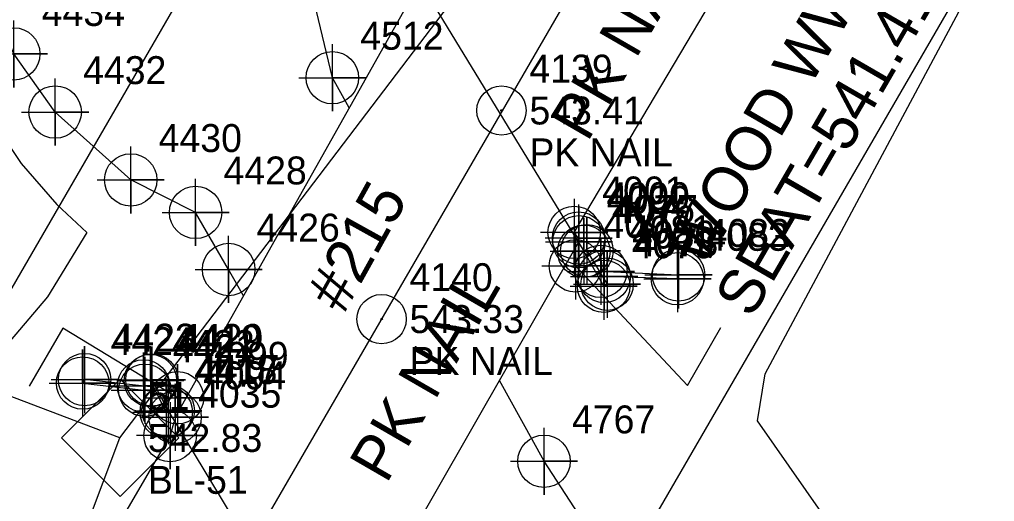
# Model space of a CAD drawing. Extents: x 1653123 to 1656194, y 596584 to 600233.
# Drawn here: x 1653723.1 to 1653810.3, y 598013.1 to 598056.2 of the extents above; entities that cross this region are included whole.
import ezdxf

# ---------------------------------------------------------------- set-up
doc = ezdxf.new("R2010")
doc.units = 0
for name, color, linetype in [('CTL Supplemental Horizontal and Vertical CELL', 7, 'Continuous'), ('CTL Supplemental Horizontal and Vertical Cogo Comment', 7, 'Continuous'), ('CTL Supplemental Horizontal and Vertical Cogo Elevation', 7, 'Continuous'), ('CTL Supplemental Horizontal and Vertical Cogo Number', 7, 'Continuous'), ('Exist Horizontal Alignment', 7, 'Continuous'), ('Exist Horizontal Baseline Alignment', 7, 'Continuous'), ('Exist Horizontal Baseline Alignment Station Label', 7, 'Continuous'), ('Exist Hydro Jurisdictional Stream or Body of Water', 7, 'Continuous'), ('Exist Hydro Stream or Body of Water Cogo Number', 7, 'Continuous'), ('Exist Property Iron Pin CELL', 7, 'Continuous'), ('Exist Property Iron Pin Cogo Comment', 7, 'Continuous'), ('Exist Property Iron Pin Cogo Elevation', 7, 'Continuous'), ('Exist Property Iron Pin Cogo Number', 7, 'Continuous'), ('Exist Property Iron Pin Text', 7, 'Continuous'), ('Exist Right of Way Line', 7, 'Continuous'), ('Exist Roads EOP Cogo Point CELL', 7, 'Continuous'), ('Exist Structure Major Bridge Seat Top Elevation', 7, 'Continuous'), ('Exist Structure Major Bridge WW Text', 7, 'Continuous'), ('Exist Structure Major Deck Tunnel Box Culvert', 7, 'Continuous'), ('Exist Structure Major Deck Tunnel Box Culvert Text', 7, 'Continuous'), ('Exist Vegetation Woods Line', 7, 'Continuous'), ('Prop Approach Slab Hatching', 7, 'Continuous'), ('Prop Conc Shoulder Berm Gutter', 7, 'Continuous'), ('Prop Guardrail Anchor Unit CELL', 7, 'Continuous'), ('Prop Horizontal Alignment', 7, 'Continuous'), ('Prop Horizontal Alignment Station Label', 7, 'Continuous'), ('Prop Horizontal Alignment Tick Label', 7, 'Continuous'), ('Prop Horizontal Alignment Tick Large', 7, 'Continuous'), ('Prop Horizontal Alignment Tick Small', 7, 'Continuous'), ('Prop Roadway Bridge', 7, 'Continuous'), ('Prop Superelevation  Arrow CELL', 7, 'Continuous')]:
    doc.layers.add(name, color=color, linetype=linetype)

msp = doc.modelspace()

# ---------------------------------------------------------------- linework, layer by layer
at = {"layer": 'CTL Supplemental Horizontal and Vertical CELL'}
msp.add_line((1653732.119, 598018.788), (1653732.119, 598018.788), dxfattribs=at)
msp.add_line((1653732.119, 598018.788), (1653732.119, 598018.788), dxfattribs=at)
msp.add_lwpolyline([(1653726.904, 598018.806), (1653732.146, 598024.047), (1653737.396, 598018.797), (1653732.155, 598013.556)], close=True, dxfattribs=at)
msp.add_lwpolyline([(1653726.904, 598018.806), (1653732.146, 598024.047), (1653737.396, 598018.797), (1653732.155, 598013.556)], close=True, dxfattribs=at)
at = {"layer": 'Exist Horizontal Alignment'}
msp.add_line((1653731.562, 597988.043), (1653850.42, 598193.455), dxfattribs=at)
at = {"layer": 'Exist Horizontal Baseline Alignment'}
for p, q in [((1653732.119, 598018.788), (1653909.758, 598252.908)), ((1653570.02, 597590.969), (1653732.119, 598018.788))]:
    msp.add_line(p, q, dxfattribs=at)
at = {"layer": 'Exist Horizontal Baseline Alignment Station Label'}
msp.add_line((1653732.119, 598018.788), (1653694.859, 598032.906), dxfattribs=at)
at = {"layer": 'Exist Hydro Jurisdictional Stream or Body of Water'}
for points in [[(1653752.596, 598048.33), (1653751.106, 598051.034), (1653748.622, 598061.502), (1653747.508, 598068.196), (1653746.66, 598076.934), (1653747.243, 598081.733), (1653747.986, 598099.401), (1653743.287, 598114.123), (1653741.057, 598120.621)], [(1653743.157, 598031.517), (1653741.838, 598033.867), (1653738.884, 598038.977), (1653733.087, 598041.881), (1653726.332, 598047.958), (1653722.632, 598053.165), (1653719.921, 598059.44), (1653713.165, 598067.917), (1653711.556, 598075.693), (1653711.811, 598079.729), (1653711.131, 598085.335)], [(1653740.514, 597810.783), (1653744.472, 597825.192), (1653752.654, 597842.937), (1653766.87, 597862.079), (1653774.242, 597884.581), (1653779.209, 597901.216), (1653784.802, 597926.151), (1653788.222, 597952.968), (1653784.153, 597976.205), (1653781.486, 597999.079), (1653770.026, 598016.697), (1653766.044, 598023.924)]]:
    msp.add_lwpolyline(points, dxfattribs=at)
at = {"layer": 'Exist Property Iron Pin CELL'}
for centre, radius in [((1653766.224, 598048.096), 2.203), ((1653766.224, 598048.096), 2.203), ((1653766.224, 598048.096), 0.0707), ((1653766.224, 598048.096), 0.0707), ((1653755.508, 598029.427), 2.203), ((1653755.508, 598029.427), 2.203), ((1653755.508, 598029.427), 0.0707), ((1653755.508, 598029.427), 0.0707)]:
    msp.add_circle(centre, radius, dxfattribs=at)
at = {"layer": 'Exist Right of Way Line'}
for p, q in [((1653705.596, 598003.068), (1653824.453, 598208.48)), ((1653757.529, 597973.018), (1653876.386, 598178.43))]:
    msp.add_line(p, q, dxfattribs=at)
at = {"layer": 'Exist Roads EOP Cogo Point CELL'}
for points in [[(1653772.726, 598040.188), (1653772.726, 598034.188), (1653772.726, 598037.188), (1653775.726, 598037.188), (1653769.726, 598037.188)], [(1653773.119, 598039.676), (1653773.119, 598033.676), (1653773.119, 598036.676), (1653776.119, 598036.676), (1653770.119, 598036.676)], [(1653736.607, 598022), (1653736.607, 598016), (1653736.607, 598019), (1653739.607, 598019), (1653733.607, 598019)]]:
    msp.add_lwpolyline(points, dxfattribs=at)
for centre in [(1653772.726, 598037.188), (1653773.119, 598036.676), (1653736.607, 598019)]:
    msp.add_circle(centre, 2.344, dxfattribs=at)
at = {"layer": 'Exist Structure Major Bridge Seat Top Elevation'}
for points in [[(1653772.836, 598034.184), (1653782.838, 598023.471), (1653785.845, 598028.663)], [(1653737.263, 598022.388), (1653727.026, 598028.604), (1653724.02, 598023.412)]]:
    msp.add_lwpolyline(points, dxfattribs=at)
at = {"layer": 'Exist Structure Major Deck Tunnel Box Culvert'}
for points in [[(1653758.793, 598059.369), (1653737.049, 598020.636)], [(1653750.814, 597997.291), (1653773.15, 598036.35)]]:
    msp.add_lwpolyline(points, dxfattribs=at)
at = {"layer": 'Exist Vegetation Woods Line'}
for points in [[(1653772.69, 597855.659), (1653780.909, 597872.984), (1653787.83, 597901.293), (1653791.961, 597923.72), (1653796.55, 597945.524), (1653799.728, 597979.56), (1653801.787, 597996.223), (1653796.294, 598010.028), (1653789.109, 598020.31), (1653789.788, 598024.526), (1653810.305, 598062.923), (1653854.435, 598139.764), (1653881.65, 598185.926), (1653890.132, 598190.266), (1653890.781, 598172.436), (1653888.254, 598125.228), (1653881.516, 598039.211), (1653880.393, 597979.917), (1653882.927, 597907.141), (1653887.551, 597812.438), (1653892.774, 597769.351), (1653892.797, 597738.525)], [(1653717.78, 598061.155), (1653719.712, 598048.676), (1653723.279, 598043.338), (1653726.476, 598039.693), (1653729.156, 598037.169), (1653725.66, 598031.427), (1653686.391, 597985.111), (1653672.043, 597936.27), (1653661.326, 597915.511)]]:
    msp.add_lwpolyline(points, dxfattribs=at)
at = {"layer": 'Prop Approach Slab Hatching'}
for points in [[(1653769.836, 598034.184), (1653775.836, 598034.184), (1653772.836, 598034.184), (1653772.836, 598037.184), (1653772.836, 598031.184)], [(1653734.263, 598022.388), (1653740.263, 598022.388), (1653737.263, 598022.388), (1653737.263, 598025.388), (1653737.263, 598019.388)]]:
    msp.add_lwpolyline(points, dxfattribs=at)
for centre in [(1653772.836, 598034.184), (1653737.263, 598022.388)]:
    msp.add_circle(centre, 2.344, dxfattribs=at)
at = {"layer": 'Prop Conc Shoulder Berm Gutter'}
for points in [[(1653773.15, 598036.35), (1653773.119, 598036.676), (1653772.726, 598037.188), (1653794.44, 598073.843), (1653816.897, 598112.323), (1653839.541, 598150.793), (1653856.887, 598180.317), (1653871.823, 598206.021), (1653894.448, 598243.912), (1653917.39, 598282.615), (1653941.959, 598322.784), (1653953.154, 598342.488), (1653957.769, 598344.372), (1653957.983, 598346.456), (1653959.261, 598348.625), (1653971.076, 598367.128), (1653990.971, 598397.837)], [(1653736.935, 598020.212), (1653736.607, 598019), (1653719.197, 597989.182), (1653700.606, 597956.072), (1653684.638, 597926.74), (1653670.295, 597899.629), (1653655.341, 597870.975), (1653640.409, 597841.446), (1653625.564, 597809.568), (1653616.437, 597790.926), (1653615.549, 597790.139), (1653613.35, 597786.395), (1653606.899, 597772.908), (1653600.392, 597757.831), (1653598.645, 597751.546), (1653587.792, 597725.217), (1653577.727, 597701.576), (1653574.752, 597692.208), (1653558.963, 597651.013), (1653542.076, 597605.708)]]:
    msp.add_lwpolyline(points, dxfattribs=at)
at = {"layer": 'Prop Guardrail Anchor Unit CELL'}
for points in [[(1653719.632, 598053.165), (1653725.632, 598053.165), (1653722.632, 598053.165), (1653722.632, 598050.165), (1653722.632, 598056.165)], [(1653748.106, 598051.034), (1653754.106, 598051.034), (1653751.106, 598051.034), (1653751.106, 598048.034), (1653751.106, 598054.034)], [(1653723.332, 598047.958), (1653729.332, 598047.958), (1653726.332, 598047.958), (1653726.332, 598044.958), (1653726.332, 598050.958)], [(1653730.087, 598041.881), (1653736.087, 598041.881), (1653733.087, 598041.881), (1653733.087, 598038.881), (1653733.087, 598044.881)], [(1653735.884, 598038.977), (1653741.884, 598038.977), (1653738.884, 598038.977), (1653738.884, 598035.977), (1653738.884, 598041.977)], [(1653738.838, 598033.867), (1653744.838, 598033.867), (1653741.838, 598033.867), (1653741.838, 598030.867), (1653741.838, 598036.867)], [(1653767.026, 598016.697), (1653773.026, 598016.697), (1653770.026, 598016.697), (1653770.026, 598013.697), (1653770.026, 598019.697)]]:
    msp.add_lwpolyline(points, dxfattribs=at)
for centre in [(1653722.632, 598053.165), (1653751.106, 598051.034), (1653726.332, 598047.958), (1653733.087, 598041.881), (1653738.884, 598038.977), (1653741.838, 598033.867), (1653770.026, 598016.697)]:
    msp.add_circle(centre, 2.344, dxfattribs=at)
at = {"layer": 'Prop Horizontal Alignment Station Label'}
for points in [[(1653770.584, 598035.496), (1653776.584, 598035.496), (1653773.584, 598035.496), (1653773.584, 598038.496), (1653773.584, 598032.496)], [(1653770.856, 598035.541), (1653776.856, 598035.541), (1653773.856, 598035.541), (1653773.856, 598038.541), (1653773.856, 598032.541)], [(1653772.101, 598033.7), (1653778.101, 598033.7), (1653775.101, 598033.7), (1653775.101, 598036.7), (1653775.101, 598030.7)], [(1653772.4, 598033.241), (1653778.4, 598033.241), (1653775.4, 598033.241), (1653775.4, 598036.241), (1653775.4, 598030.241)], [(1653779.052, 598033.383), (1653785.052, 598033.383), (1653782.052, 598033.383), (1653782.052, 598036.383), (1653782.052, 598030.383)], [(1653772.36, 598032.366), (1653778.36, 598032.366), (1653775.36, 598032.366), (1653775.36, 598035.366), (1653775.36, 598029.366)], [(1653772.663, 598032.552), (1653778.663, 598032.552), (1653775.663, 598032.552), (1653775.663, 598035.552), (1653775.663, 598029.552)], [(1653778.953, 598033.039), (1653784.953, 598033.039), (1653781.953, 598033.039), (1653781.953, 598036.039), (1653781.953, 598030.039)], [(1653725.79, 598023.703), (1653731.79, 598023.703), (1653728.79, 598023.703), (1653728.79, 598026.703), (1653728.79, 598020.703)], [(1653725.961, 598024.014), (1653731.961, 598024.014), (1653728.961, 598024.014), (1653728.961, 598027.014), (1653728.961, 598021.014)], [(1653731.844, 598023.921), (1653737.844, 598023.921), (1653734.844, 598023.921), (1653734.844, 598026.921), (1653734.844, 598020.921)], [(1653731.979, 598023.988), (1653737.979, 598023.988), (1653734.979, 598023.988), (1653734.979, 598026.988), (1653734.979, 598020.988)], [(1653731.233, 598023.445), (1653737.233, 598023.445), (1653734.233, 598023.445), (1653734.233, 598026.445), (1653734.233, 598020.445)], [(1653731.347, 598023.059), (1653737.347, 598023.059), (1653734.347, 598023.059), (1653734.347, 598026.059), (1653734.347, 598020.059)], [(1653733.261, 598021.108), (1653739.261, 598021.108), (1653736.261, 598021.108), (1653736.261, 598024.108), (1653736.261, 598018.108)], [(1653733.437, 598021.22), (1653739.437, 598021.22), (1653736.437, 598021.22), (1653736.437, 598024.22), (1653736.437, 598018.22)]]:
    msp.add_lwpolyline(points, dxfattribs=at)
for centre in [(1653773.584, 598035.496), (1653773.856, 598035.541), (1653775.101, 598033.7), (1653775.4, 598033.241), (1653781.953, 598033.039), (1653782.052, 598033.383), (1653775.36, 598032.366), (1653775.663, 598032.552), (1653728.79, 598023.703), (1653728.961, 598024.014), (1653734.233, 598023.445), (1653734.844, 598023.921), (1653734.979, 598023.988), (1653734.347, 598023.059), (1653736.261, 598021.108), (1653736.437, 598021.22)]:
    msp.add_circle(centre, 2.344, dxfattribs=at)
at = {"layer": 'Prop Horizontal Alignment Tick Large'}
for points in [[(1653770.15, 598036.35), (1653776.15, 598036.35), (1653773.15, 598036.35), (1653773.15, 598039.35), (1653773.15, 598033.35)], [(1653734.049, 598020.636), (1653740.049, 598020.636), (1653737.049, 598020.636), (1653737.049, 598023.636), (1653737.049, 598017.636)]]:
    msp.add_lwpolyline(points, dxfattribs=at)
for centre in [(1653773.15, 598036.35), (1653737.049, 598020.636)]:
    msp.add_circle(centre, 2.344, dxfattribs=at)
at = {"layer": 'Prop Superelevation  Arrow CELL'}
for points in [[(1653758.615, 598061.179), (1653757.317, 598063.393), (1653756.891, 598063.257), (1653758.145, 598060.87), (1653773.584, 598035.496)], [(1653773.856, 598035.541), (1653775.663, 598032.552), (1653775.36, 598032.366), (1653773.584, 598035.496)], [(1653774.965, 598033.706), (1653782.052, 598033.383), (1653781.953, 598033.039), (1653775.243, 598033.246)], [(1653735.133, 598023.348), (1653728.961, 598024.014), (1653728.79, 598023.703), (1653735.336, 598022.945)], [(1653736.261, 598021.108), (1653734.844, 598023.921), (1653734.979, 598023.988), (1653736.437, 598021.22)], [(1653736.437, 598021.22), (1653751.877, 597995.633), (1653753.359, 597993.259), (1653753.202, 597993.102), (1653751.69, 597995.386)]]:
    msp.add_lwpolyline(points, dxfattribs=at)

# ---------------------------------------------------------------- texts
at = {"layer": 'CTL Supplemental Horizontal and Vertical Cogo Comment'}
msp.add_text('BL-51', height=2.5, dxfattribs=at).set_placement((1653734.619, 598013.788))
at = {"layer": 'CTL Supplemental Horizontal and Vertical Cogo Elevation'}
msp.add_text('542.83', height=2.5, dxfattribs=at).set_placement((1653734.619, 598017.538))
at = {"layer": 'CTL Supplemental Horizontal and Vertical Cogo Number'}
msp.add_text('51', height=2.5, dxfattribs=at).set_placement((1653734.619, 598021.288))
msp.add_text('51', height=2.5, dxfattribs=at).set_placement((1653734.619, 598021.288))
at = {"layer": 'Exist Hydro Stream or Body of Water Cogo Number'}
for s, p in [('4434', (1653725.132, 598055.665)), ('4512', (1653753.606, 598053.534)), ('4432', (1653728.832, 598050.458)), ('4430', (1653735.587, 598044.381)), ('4428', (1653741.384, 598041.478)), ('4426', (1653744.338, 598036.367)), ('4767', (1653772.526, 598019.197))]:
    msp.add_text(s, height=2.5, dxfattribs=at).set_placement(p)
at = {"layer": 'Exist Property Iron Pin Cogo Comment'}
for p in [(1653768.724, 598043.096), (1653758.008, 598024.427)]:
    msp.add_text('PK NAIL', height=2.5, dxfattribs=at).set_placement(p)
at = {"layer": 'Exist Property Iron Pin Cogo Elevation'}
for s, p in [('543.41', (1653768.724, 598046.846)), ('543.33', (1653758.008, 598028.177))]:
    msp.add_text(s, height=2.5, dxfattribs=at).set_placement(p)
at = {"layer": 'Exist Property Iron Pin Cogo Number'}
for s, p in [('4139', (1653768.724, 598050.596)), ('4139', (1653768.724, 598050.596)), ('4140', (1653758.008, 598031.927)), ('4140', (1653758.008, 598031.927))]:
    msp.add_text(s, height=2.5, dxfattribs=at).set_placement(p)
at = {"layer": 'Exist Property Iron Pin Text'}
for p in [(1653773.912, 598045.186), (1653755.94, 598014.612)]:
    msp.add_text('PK NAIL', height=4, rotation=59.9255, dxfattribs=at).set_placement(p)
at = {"layer": 'Exist Structure Major Bridge Seat Top Elevation'}
msp.add_text("SEAT=541.41'", height=4, rotation=59.9255, dxfattribs=at).set_placement((1653788.578, 598029.391))
at = {"layer": 'Exist Structure Major Bridge WW Text'}
msp.add_text('WOOD WWs', height=4, rotation=59.92548, dxfattribs=at).set_placement((1653784.39, 598033.916))
at = {"layer": 'Exist Structure Major Deck Tunnel Box Culvert Text'}
msp.add_text('#215', height=4, rotation=60.94542, dxfattribs=at).set_placement((1653752.132, 598029.802))
at = {"layer": 'Prop Horizontal Alignment'}
for s, p in [('4001', (1653775.226, 598039.688)), ('4000', (1653775.619, 598039.176)), ('4035', (1653739.107, 598021.5))]:
    msp.add_text(s, height=2.5, dxfattribs=at).set_placement(p)
at = {"layer": 'Prop Horizontal Alignment Tick Label'}
for s, p in [('4077', (1653776.356, 598038.042)), ('4076', (1653776.084, 598037.996)), ('4081', (1653777.601, 598036.2)), ('4080', (1653777.9, 598035.741)), ('4083', (1653784.453, 598035.539)), ('4082', (1653784.552, 598035.883)), ('4079', (1653777.86, 598034.866)), ('4078', (1653778.163, 598035.052)), ('4424', (1653731.29, 598026.203)), ('4423', (1653731.461, 598026.514)), ('4422', (1653736.733, 598025.945)), ('4419', (1653737.344, 598026.421)), ('4420', (1653737.479, 598026.488)), ('4421', (1653736.847, 598025.559)), ('4418', (1653738.761, 598023.608)), ('4417', (1653738.937, 598023.72))]:
    msp.add_text(s, height=2.5, dxfattribs=at).set_placement(p)
at = {"layer": 'Prop Horizontal Alignment Tick Small'}
for s, p in [('4092', (1653775.65, 598038.851)), ('4094', (1653739.549, 598023.136))]:
    msp.add_text(s, height=2.5, dxfattribs=at).set_placement(p)
at = {"layer": 'Prop Roadway Bridge'}
for s, p in [('4097', (1653775.336, 598036.684)), ('4099', (1653739.763, 598024.889))]:
    msp.add_text(s, height=2.5, dxfattribs=at).set_placement(p)

doc.saveas('drawing.dxf')
